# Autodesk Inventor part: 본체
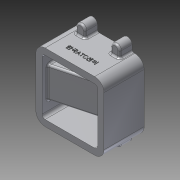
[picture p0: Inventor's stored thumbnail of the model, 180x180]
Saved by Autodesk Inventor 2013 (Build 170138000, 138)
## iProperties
Created: 2018-01
Part Number: 본체
Material: 알루미늄 6061
Document SubType Name: Modeling
Designer: Administrator
Density: 2.71 g/cm^3
Mass: 999 g
Surface Area: 834.575 cm^2
Volume: 368.635 cm^3
Author: Administrator
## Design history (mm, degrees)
sketch "스케치1"
  geometry: L1 (55, 55)-(-55, 55); L2 (-55, 55)-(-55, -55); L3 (-55, -55)-(55, -55); L4 (55, -55)-(55, 55); L5 (55, 55)-(-55, -55); L6 (-55, 55)-(55, -55); 1 further point
  constraints: 12 end point, 2 midpoint, 2 parallel, 1 horizontal, 1 perpendicular
  dimensions: "d0" = 110 distance of L3.end L2.end; "d1" = 110 distance of L2.end L1.end
extrude "돌출1" new body sketch "스케치1" distance "d2" = 65; taper "d3" = 0 deg
sketch "스케치2"
  geometry: L1 (-55, -55)-(55, -55) reference; L2 (55, -55)-(55, 55) reference; L3 (55, 55)-(-55, 55) reference; L4 (-55, 55)-(-55, -55) reference; L5 (-45, 45)-(45, 45); L6 (45, 45)-(45, -45); L7 (45, -45)-(-45, -45); L8 (-45, -45)-(-45, 45); 1 further point
  constraints: 8 end point, 3 other
  dimensions: "d4" = 10 distance between parallel lines of L2 L6
extrude "돌출2" cut sketch "스케치2" distance "d5" = 65; taper "d6" = 0 deg
sketch "스케치3"
  geometry: L1 (55, 55)-(-55, 55) reference; L2 (-55, -55)-(55, -55) reference; L3 (-35.5, 55)-(-35.5, 65); L4 (-20.5, 65)-(-20.5, 55); L5 (-55, 55)-(-55, -55) reference; L6 (55, -55)-(55, 55) reference; L7 (-55, 0)-(55, 0); L8 (0, 55)-(0, -55); L9 (35.5, 55)-(35.5, 65); L10 (20.5, 65)-(20.5, 55); L11 (20.5, -65)-(20.5, -55); L12 (35.5, -55)-(35.5, -65); L13 (-35.5, -55)-(-35.5, -65); L14 (-20.5, -65)-(-20.5, -55); L15 (-35.5, 55)-(-20.5, 55); L16 (20.5, 55)-(35.5, 55); L17 (-35.5, -55)-(-20.5, -55); L18 (20.5, -55)-(35.5, -55); A1 r 7.5 centre (-28, 65) between (-20.5, 65) and (-35.5, 65); A2 r 7.5 centre (28, 65) between (35.5, 65) and (20.5, 65); A3 r 7.5 centre (28, -65) between (20.5, -65) and (35.5, -65); A4 r 7.5 centre (-28, -65) between (-35.5, -65) and (-20.5, -65); 1 further point
  constraints: 28 end point, 15 symmetric about line, 8 point on circle, 4 centre point, 4 collinear, 4 midpoint, 2 perpendicular, 2 point on line, 2 tangent, 3 other
  dimensions: "d7" = 7.5 radius of A1; "d9" = 10 distance of L3.start L3.end; "d10" = 27 horizontal distance of L1.end A1.centre
extrude "돌출3" join sketch "스케치3" distance "d11" = 20; taper "d12" = 0 deg
sketch "스케치4"
  geometry: L1 (-45, 0)-(-45, -65) reference; L2 (-45, 0)-(45, 0) reference; L3 (-45, -56.436)-(35, -35); L4 (35, -35)-(35, 0); L5 (55, 0)-(55, -65) reference; 1 further point
  constraints: 4 end point, 2 point on line, 1 perpendicular
  dimensions: "d13" = 20 distance between parallel lines of L5 L4; "d14" = 30 vertical distance of L5.end L3.end; "d15" = 105 deg angle of L1 L3
extrude "돌출4" join sketch "스케치4" stored distance "d16" = 50; taper "d17" = 0 deg
sketch "스케치5"
  geometry: L1 (-55, 55)-(-55, -55) reference; L2 (-55, 7.5)-(-36, 7.5); L3 (-36, 7.5)-(-36, 16); L4 (-36, 16)-(-22, 16); L5 (-22, 16)-(-22, 20); L6 (-22, 20)-(25, 20); L7 (25, 20)-(25, 15); L8 (25, 15)-(30, 15); L9 (30, 15)-(30, 0); L10 (30, 0)-(-55, 0); L11 (-55, 0)-(-55, 7.5); 2 further points
  constraints: 20 end point, 6 parallel, 2 midpoint, 2 perpendicular, 1 collinear, 1 horizontal alignment, 1 point on line
  dimensions: "d18" = 30 diameter of L8 L10; "d20" = 40 diameter of L6 L10; "d21" = 32 diameter of L4 L10; "d22" = 15 diameter of L2 L10; "d23" = 19 distance of L2.start L2.end; "d24" = 14 distance of L3.end L4.end; "d25" = 47 distance of L5.end L6.end; "d26" = 5 distance of L7.end L8.end
revolve "회전1" sketch "스케치5" stored, may be unused: angle "d27" = 90 deg
sketch "스케치6"
  geometry: L1 (35, -35)-(-45, -56.436) reference; L2 (20, -33.843)-(-55, -53.939); L3 (-55, -35.939)-(-17, -25.757); L4 (-17, -25.757)-(-17, -10); L5 (20, -10)-(20, -33.843); L6 (25, -20)-(-22, -20) reference; L7 (-55, 0)-(-55, -65) reference; L8 (-17, -10)-(20, -10); L9 (-55, -53.939)-(-55, -35.939); 1 further point
  constraints: 12 end point, 3 parallel, 2 point on line, 1 collinear, 1 vertical
  dimensions: "d28" = 5 distance between parallel lines of L1 L2; "d29" = 5 distance from line of L4 L6.end; "d30" = 5 distance from line of L6.start L5; "d31" = 18 distance of L2.end L3.start; "d32" = 10 distance between parallel lines of L6 L8
extrude "돌출5" cut sketch "스케치6" stored distance "d33" = 30; taper "d34" = 0 deg
fillet "모깎기1" dims "d35" = 15, "d36" = 5, "d37" = 3, "d38" = 1
fillet "모깎기2" dims "d39" = 3
sketch "스케치7"
  geometry: L1 (-40, -45)-(40, -45) reference; L2 (45, -40)-(45, 40) reference; L3 (40, 45)-(-40, 45) reference; L4 (-45, 40)-(-45, 28) reference; L5 (-42, 25)-(32, 25) reference; L6 (35, 22)-(35, -22) reference; L7 (32, -25)-(-42, -25) reference; L8 (-45, -28)-(-45, -40) reference; L9 (35.5, 65)-(35.5, 58) reference; L10 (38.5, 55)-(40, 55) reference; L11 (55, 40)-(55, -40) reference; L12 (40, -55)-(38.5, -55) reference; L13 (35.5, -58)-(35.5, -65) reference; L14 (20.5, -65)-(20.5, -58) reference; L15 (17.5, -55)-(-17.5, -55) reference; L16 (-20.5, -58)-(-20.5, -65) reference; L17 (-35.5, -65)-(-35.5, -58) reference; L18 (-38.5, -55)-(-40, -55) reference; L19 (-55, -40)-(-55, -7.5) reference; L20 (-55, -7.5)-(-36, -7.5) reference; L21 (-36, -7.5)-(-36, -15) reference; L22 (-35, -16)-(-22, -16) reference; L23 (-22, -16)-(-22, -19) reference; L24 (-21, -20)-(24, -20) reference; L25 (25, -19)-(25, -15) reference; L26 (25, -15)-(29, -15) reference; L27 (30, -14)-(30, 14) reference; L28 (29, 15)-(25, 15) reference; L29 (25, 15)-(25, 19) reference; L30 (24, 20)-(-21, 20) reference; L31 (-22, 19)-(-22, 16) reference; L32 (-22, 16)-(-35, 16) reference; L33 (-36, 15)-(-36, 7.5) reference; L34 (-36, 7.5)-(-55, 7.5) reference; L35 (-55, 7.5)-(-55, 40) reference; L36 (-40, 55)-(-38.5, 55) reference; L37 (-35.5, 58)-(-35.5, 65) reference; L38 (-20.5, 65)-(-20.5, 58) reference; L39 (-17.5, 55)-(17.5, 55) reference; L40 (20.5, 58)-(20.5, 65) reference; A1 r 5 centre (-40, -40) between (-45, -40) and (-40, -45) reference; A2 r 5 centre (40, -40) between (40, -45) and (45, -40) reference; A3 r 5 centre (40, 40) between (45, 40) and (40, 45) reference; A4 r 5 centre (-40, 40) between (-40, 45) and (-45, 40) reference; A5 r 3 centre (-42, 28) between (-45, 28) and (-42, 25) reference; A6 r 3 centre (32, 22) between (35, 22) and (32, 25) reference; A7 r 3 centre (32, -22) between (32, -25) and (35, -22) reference; A8 r 3 centre (-42, -28) between (-42, -25) and (-45, -28) reference; A9 r 7.5 centre (28, 65) between (35.5, 65) and (20.5, 65) reference; A10 r 3 centre (38.5, 58) between (35.5, 58) and (38.5, 55) reference; A11 r 15 centre (40, 40) between (55, 40) and (40, 55) reference; A12 r 15 centre (40, -40) between (40, -55) and (55, -40) reference; A13 r 3 centre (38.5, -58) between (38.5, -55) and (35.5, -58) reference; A14 r 7.5 centre (28, -65) between (20.5, -65) and (35.5, -65) reference; A15 r 3 centre (17.5, -58) between (20.5, -58) and (17.5, -55) reference; A16 r 3 centre (-17.5, -58) between (-17.5, -55) and (-20.5, -58) reference; A17 r 7.5 centre (-28, -65) between (-35.5, -65) and (-20.5, -65) reference; A18 r 3 centre (-38.5, -58) between (-35.5, -58) and (-38.5, -55) reference; A19 r 15 centre (-40, -40) between (-55, -40) and (-40, -55) reference; A20 r 1 centre (-35, -15) between (-36, -15) and (-35, -16) reference; A21 r 1 centre (-21, -19) between (-22, -19) and (-21, -20) reference; A22 r 1 centre (24, -19) between (24, -20) and (25, -19) reference; A23 r 1 centre (29, -14) between (29, -15) and (30, -14) reference; A24 r 1 centre (29, 14) between (30, 14) and (29, 15) reference; A25 r 1 centre (24, 19) between (25, 19) and (24, 20) reference; A26 r 1 centre (-21, 19) between (-21, 20) and (-22, 19) reference; A27 r 1 centre (-35, 15) between (-35, 16) and (-36, 15) reference; A28 r 15 centre (-40, 40) between (-40, 55) and (-55, 40) reference; A29 r 3 centre (-38.5, 58) between (-38.5, 55) and (-35.5, 58) reference; A30 r 7.5 centre (-28, 65) between (-20.5, 65) and (-35.5, 65) reference; A31 r 3 centre (-17.5, 58) between (-20.5, 58) and (-17.5, 55) reference; A32 r 3 centre (17.5, 58) between (17.5, 55) and (20.5, 58) reference; 5 further points
  constraints: 4 coincident
hole "구멍1" sketch "스케치7" at (-28, 65), (28, 65), (-28, -65), (28, -65) diameter "d40" = 3.242; stored, may be unused: countersink angle "d44" = 90 deg, drill point angle "d46" = 118 deg; dims "d41" = 9, "d42" = 4, "d43" = 2, "d45" = 11
chamfer "모따기1" distance "d47" = 1; stored, may be unused: second distance "d48" = 2, angle "d49" = 45 deg
sketch "스케치8" dims "d0" = 110, "d1" = 110
  geometry: L1 (-7.387, -41.398)-(42.387, -41.398); L2 (42.387, -41.398)-(42.387, -48.602); L3 (42.387, -48.602)-(-7.387, -48.602); L4 (-7.387, -48.602)-(-7.387, -41.398); L5 (-37.5, 0)-(-37.5, -65) reference; L6 (57.5, -65)-(-22.5, -65) reference; 6 further points
  constraints: 4 midpoint, 2 horizontal alignment, 2 vertical alignment, 2 other
  dimensions: "d50" = 49.77477 distance of L1.start L1.end; "d52" = 7.20489 distance of L1.end L2.end; "d53" = 55 distance from line of L5 point (17.5, -45); "d54" = 20 distance from line of L6 point (17.5, -45)
feature "엠보싱1" sketch "스케치8" dims "d0" = 110, "d1" = 110, "d55" = 0.5, "d56" = 0
node "솔리드1"
node "투영된 루프1"
node "절단 모서리 투영1"
